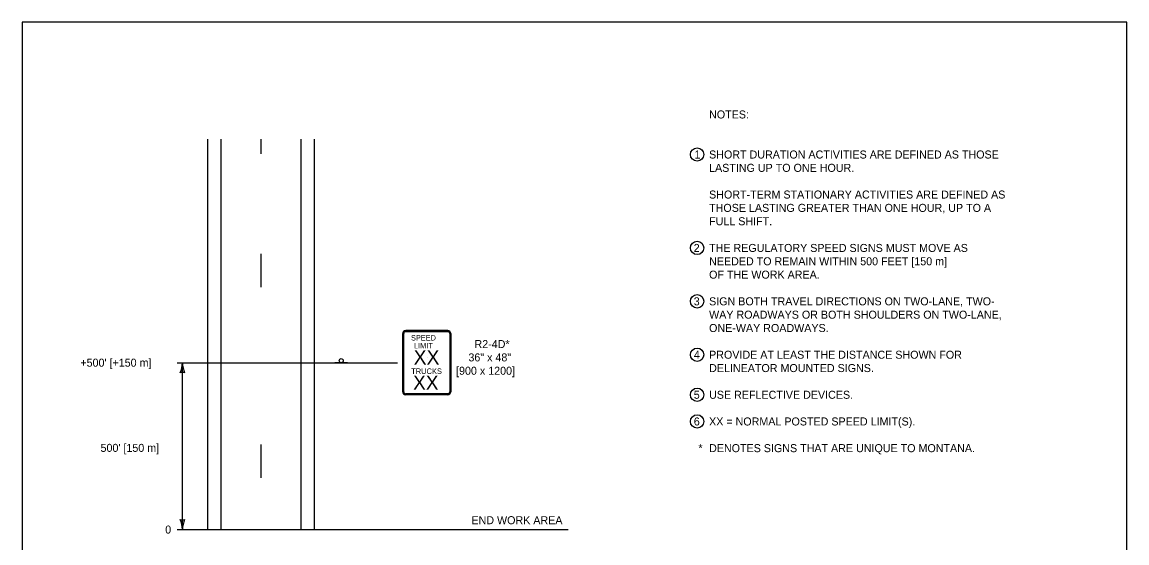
# Model space of a CAD drawing. Extents: x 49991.4 to 50021, y 49987.6 to 50011.4.
# Drawn here: x 50000.34 to 50008.61, y 50007.36 to 50011.26 of the extents above; entities that cross this region are included whole.
import ezdxf

# ---------------------------------------------------------------- set-up
doc = ezdxf.new("R2010")
doc.units = 0
for name, color, linetype in [('Level 1', 7, 'Continuous'), ('Level 2', 7, 'Continuous'), ('Level 3', 7, 'Continuous')]:
    doc.layers.add(name, color=color, linetype=linetype)

msp = doc.modelspace()

# ---------------------------------------------------------------- linework, layer by layer
at = {"layer": 'Level 1'}
for p, q in [((50001.7269, 50008.5955), (50001.7269, 50010.3861)), ((50001.8269, 50008.5955), (50001.8269, 50010.3861)), ((50002.1269, 50010.2766), (50002.1269, 50010.3861)), ((50002.4269, 50008.5955), (50002.4269, 50010.3861)), ((50002.5269, 50008.5955), (50002.5269, 50010.3861)), ((50002.1269, 50009.2766), (50002.1269, 50009.5266)), ((50003.1876, 50008.4938), (50003.1876, 50008.9287)), ((50003.1952, 50008.4938), (50003.1952, 50008.9287)), ((50003.5251, 50008.9512), (50003.2101, 50008.9512)), ((50003.5251, 50008.9436), (50003.2101, 50008.9436)), ((50003.54, 50008.9287), (50003.54, 50008.4938)), ((50003.5476, 50008.9287), (50003.5476, 50008.4938)), ((50003.3711, 50008.7535), (50003.3711, 50008.7535)), ((50002.7749, 50008.7113), (50002.6789, 50008.7113)), ((50001.7269, 50007.4611), (50001.7269, 50008.5955)), ((50001.8269, 50007.4611), (50001.8269, 50008.5955)), ((50002.4269, 50007.4611), (50002.4269, 50008.5955)), ((50002.5269, 50007.4611), (50002.5269, 50008.5955)), ((50003.5251, 50008.4789), (50003.2101, 50008.4789)), ((50003.5251, 50008.4713), (50003.2101, 50008.4713)), ((50002.1269, 50007.8491), (50002.1269, 50008.0991))]:
    msp.add_line(p, q, dxfattribs=at)
msp.add_lwpolyline([(50008.6146, 50011.2628), (50000.3356, 50011.2628), (50000.3356, 50000.0624), (50008.6146, 50000.0624)], close=True, dxfattribs=at)
msp.add_circle((50002.7269, 50008.7265), 0.0152, dxfattribs=at)
for centre, radius, start, end in [((50003.2101, 50008.9287), 0.0225, 90, 180), ((50003.2101, 50008.9287), 0.0149, 90, 180), ((50003.5251, 50008.9287), 0.0225, 0, 90), ((50003.5251, 50008.9287), 0.0149, 0, 90), ((50003.2101, 50008.4938), 0.0225, 180, 270), ((50003.2101, 50008.4938), 0.0149, 180, 270), ((50003.5251, 50008.4938), 0.0225, 270, 0), ((50003.5251, 50008.4938), 0.0149, 270, 0)]:
    msp.add_arc(centre, radius, start, end, dxfattribs=at)
at = {"layer": 'Level 2'}
for centre in [(50005.3937, 50010.2709), (50005.3937, 50009.5709), (50005.3937, 50009.1709), (50005.3937, 50008.7709), (50005.3937, 50008.4709), (50005.3937, 50008.2709)]:
    msp.add_circle(centre, 0.05, dxfattribs=at)
at = {"layer": 'Level 3'}
for p, q in [((50001.4969, 50008.7113), (50002.9812, 50008.7113)), ((50001.5369, 50007.4611), (50001.5369, 50008.6851)), ((50002.8149, 50008.7113), (50003.1476, 50008.7113)), ((50001.4969, 50007.4611), (50004.4271, 50007.4611))]:
    msp.add_line(p, q, dxfattribs=at)
for centre, radius, start, end in [((50001.3148, 50008.7203), 0.2223, 337.45601, 357.63952), ((50001.5369, 50008.5829), 0.0548, 72.13882, 107.86118), ((50001.7696, 50008.7226), 0.233, 182.82731, 202.07716), ((50001.5369, 50007.5893), 0.0548, 252.13882, 287.86118), ((50001.3042, 50007.4496), 0.233, 2.82731, 22.07716), ((50001.759, 50007.4519), 0.2223, 157.45601, 177.63952)]:
    msp.add_arc(centre, radius, start, end, dxfattribs=at)

# ---------------------------------------------------------------- texts
at = {"layer": 'Level 1'}
for s, height, p in [('SPEED', 0.04121, (50003.2499, 50008.8771)), ('XX', 0.10831, (50003.2699, 50008.6967)), ('LIMIT', 0.04162, (50003.2717, 50008.8177)), ('TRUCKS', 0.04183, (50003.2515, 50008.6264)), ('XX', 0.10679, (50003.2655, 50008.5083))]:
    msp.add_text(s, height=height, dxfattribs=at).set_placement(p)
at = {"layer": 'Level 2'}
for s, p in [('NOTES:', (50005.4837, 50010.5409)), ('1', (50005.3743, 50010.2409)), ('SHORT DURATION ACTIVITIES ARE DEFINED AS THOSE', (50005.4837, 50010.2409)), ('LASTING UP TO ONE HOUR.', (50005.4837, 50010.1409)), ('SHORT-TERM STATIONARY ACTIVITIES ARE DEFINED AS', (50005.4837, 50009.9409)), ('THOSE LASTING GREATER THAN ONE HOUR, UP TO A', (50005.4837, 50009.8409)), ('FULL SHIFT.', (50005.4837, 50009.7409)), ('2', (50005.3685, 50009.5409)), ('THE REGULATORY SPEED SIGNS MUST MOVE AS ', (50005.4837, 50009.5409)), ('NEEDED TO REMAIN WITHIN 500 FEET [150 m] ', (50005.4837, 50009.4409)), ('OF THE WORK AREA.', (50005.4837, 50009.3409)), ('3', (50005.3685, 50009.1409)), ('SIGN BOTH TRAVEL DIRECTIONS ON TWO-LANE, TWO-', (50005.4837, 50009.1409)), ('WAY ROADWAYS OR BOTH SHOULDERS ON TWO-LANE,', (50005.4837, 50009.0409)), ('ONE-WAY ROADWAYS.', (50005.4837, 50008.9409)), ('R2-4D*', (50003.7256, 50008.8208)), ("+500' [+150 m]", (50000.7723, 50008.6813)), ('36" x 48"', (50003.6801, 50008.7208)), ('4', (50005.3697, 50008.7409)), ('PROVIDE AT LEAST THE DISTANCE SHOWN FOR ', (50005.4837, 50008.7409)), ('[900 x 1200]', (50003.5876, 50008.6208)), ('DELINEATOR MOUNTED SIGNS.', (50005.4837, 50008.6409)), ('5', (50005.3688, 50008.4409)), ('USE REFLECTIVE DEVICES.', (50005.4837, 50008.4409)), ('6', (50005.3692, 50008.2409)), ('XX = NORMAL POSTED SPEED LIMIT(S).', (50005.4837, 50008.2409)), ("500' [150 m]", (50000.9235, 50008.0431)), ('*', (50005.4039, 50008.0409)), ('DENOTES SIGNS THAT ARE UNIQUE TO MONTANA.', (50005.4837, 50008.0409)), ('END WORK AREA', (50003.7029, 50007.5011)), ('0', (50001.4081, 50007.4311))]:
    msp.add_text(s, height=0.06, dxfattribs=at).set_placement(p)

doc.saveas('drawing.dxf')
